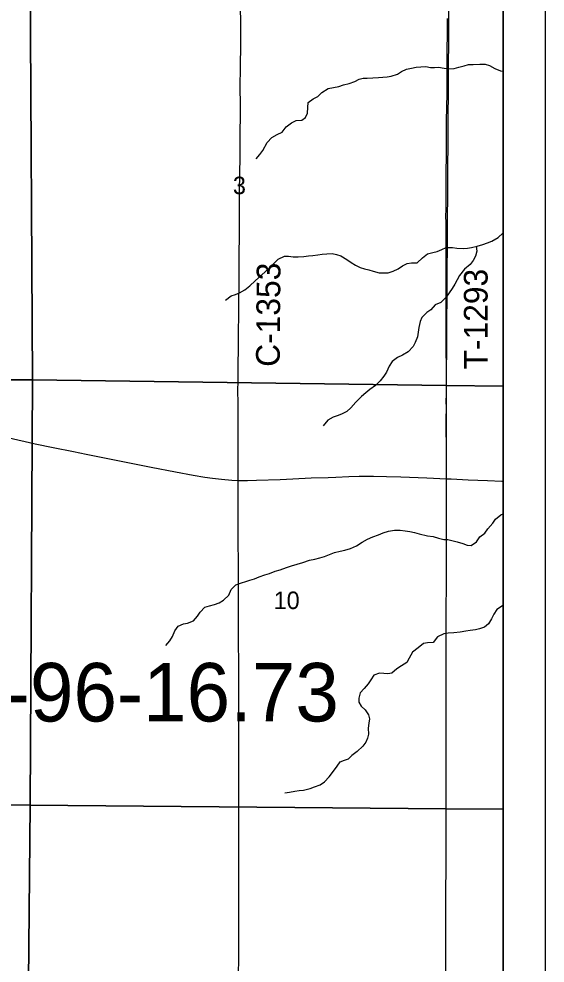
# Model space of a CAD drawing. Extents: x 0 to 70.2, y 0 to 31.4.
# Drawn here: x 7.741 to 9, y 15.952 to 18.211 of the extents above; entities that cross this region are included whole.
import ezdxf

# ---------------------------------------------------------------- set-up
doc = ezdxf.new("R2010")
doc.units = 0
for name, color, linetype in [('Default', 7, 'Continuous'), ('GM_X_County_Road', 7, 'Continuous'), ('GM_X_County_Road_Text', 7, 'Continuous'), ('GM_X_Minor_River', 7, 'Continuous'), ('GM_X_Section', 7, 'Continuous'), ('GM_X_Section_Text', 7, 'Continuous'), ('GM_X_State_Route', 7, 'Continuous'), ('GM_X_Township_Road', 7, 'Continuous'), ('GM_X_Township_Road_Text', 7, 'Continuous'), ('SH_Cut_Line', 7, 'Continuous'), ('SH_Data', 7, 'Continuous')]:
    doc.layers.add(name, color=color, linetype=linetype)

msp = doc.modelspace()

# ---------------------------------------------------------------- linework, layer by layer
at = {"layer": 'GM_X_County_Road'}
msp.add_lwpolyline([(8.2656, 17.1069), (8.2656, 17.113), (8.2658, 17.1534), (8.2658, 17.1814), (8.2656, 17.2311), (8.2655, 17.2621), (8.2655, 17.2869), (8.2653, 17.327), (8.2655, 17.3393), (8.2655, 17.3521), (8.2659, 17.386), (8.266, 17.3953), (8.2662, 17.4108), (8.2666, 17.4388), (8.2667, 17.4668), (8.267, 17.4978), (8.2676, 17.5382), (8.2679, 17.5724), (8.2681, 17.5942), (8.2681, 17.6065), (8.268, 17.622), (8.2679, 17.6282), (8.2681, 17.6438), (8.2684, 17.6653), (8.2686, 17.6748), (8.2688, 17.683), (8.2688, 17.7544), (8.2692, 17.798), (8.2707, 17.8819), (8.2708, 17.9254), (8.271, 17.9937), (8.271, 18.0154), (8.2709, 18.0372), (8.2716, 18.1056), (8.2719, 18.1398), (8.2719, 18.174), (8.2714, 18.2672)], dxfattribs=at)
at = {"layer": 'GM_X_Minor_River'}
for points in [[(8.3092, 17.8761), (8.3179, 17.8867), (8.3248, 17.8962), (8.3354, 17.9152), (8.346, 17.9269), (8.3589, 17.9345), (8.371, 17.9402), (8.3802, 17.9531), (8.3931, 17.9622), (8.4048, 17.9679), (8.4177, 17.969), (8.4272, 17.9754), (8.4314, 17.9857), (8.4321, 17.999), (8.4329, 18.0107), (8.4454, 18.0198), (8.456, 18.0251), (8.4659, 18.0346), (8.4807, 18.0441), (8.4936, 18.0467), (8.5069, 18.0494), (8.5175, 18.0528), (8.5315, 18.0562), (8.5448, 18.0611), (8.555, 18.0664), (8.5645, 18.0695), (8.5744, 18.0695), (8.5877, 18.0698), (8.6013, 18.0706), (8.6116, 18.0713), (8.6218, 18.0725), (8.6317, 18.074), (8.6468, 18.0789), (8.6563, 18.085), (8.6681, 18.0903), (8.6802, 18.0929), (8.6916, 18.0952), (8.703, 18.0963), (8.7147, 18.0967), (8.7257, 18.0948), (8.7356, 18.0948), (8.7451, 18.0955), (8.7587, 18.0929), (8.7693, 18.0914), (8.7826, 18.0925), (8.794, 18.0955), (8.8065, 18.0989), (8.8171, 18.1019), (8.8281, 18.1016), (8.8437, 18.1023), (8.8566, 18.1023), (8.8668, 18.0996), (8.8801, 18.092), (8.893, 18.0867), (8.9, 18.0862)], [(8.2351, 17.5377), (8.2487, 17.5483), (8.259, 17.5513), (8.2688, 17.5555), (8.2817, 17.5631), (8.2935, 17.5722), (8.3068, 17.5847), (8.3307, 17.6059), (8.3409, 17.6154), (8.3504, 17.6253), (8.3614, 17.6363), (8.3762, 17.6431), (8.3864, 17.6431), (8.3974, 17.6419), (8.4096, 17.6419), (8.4229, 17.6427), (8.4342, 17.6438), (8.4441, 17.6453), (8.4562, 17.6468), (8.4668, 17.648), (8.4775, 17.6487), (8.4904, 17.6495), (8.5006, 17.6476), (8.5112, 17.6441), (8.5256, 17.6354), (8.5362, 17.6278), (8.5465, 17.6217), (8.5575, 17.6164), (8.5681, 17.6134), (8.578, 17.6107), (8.5889, 17.6073), (8.6034, 17.6035), (8.6136, 17.6031), (8.6246, 17.6038), (8.6367, 17.6076), (8.6485, 17.6133), (8.6591, 17.6201), (8.6701, 17.6258), (8.6807, 17.627), (8.6936, 17.6273), (8.7065, 17.6391), (8.7183, 17.6486), (8.7316, 17.652), (8.7414, 17.6542), (8.7528, 17.6592), (8.7634, 17.6641), (8.7786, 17.6641), (8.7888, 17.6626), (8.8036, 17.6614), (8.8146, 17.6622), (8.8241, 17.6644), (8.8374, 17.6675), (8.8514, 17.6713), (8.8624, 17.6754), (8.8727, 17.6792), (8.8878, 17.6879), (8.8988, 17.6982), (8.9, 17.6977)], [(8.8353, 17.667), (8.837, 17.6549), (8.8336, 17.6436), (8.8275, 17.6333), (8.8207, 17.6235), (8.8074, 17.6125), (8.7949, 17.5973), (8.7896, 17.5867), (8.7842, 17.5764), (8.7774, 17.5658), (8.7706, 17.5556), (8.7634, 17.5453), (8.7508, 17.5328), (8.7372, 17.5271), (8.7269, 17.515), (8.7167, 17.5089), (8.7049, 17.4968), (8.7011, 17.4869), (8.6981, 17.4729), (8.6966, 17.4615), (8.6947, 17.4501), (8.6894, 17.4369), (8.6844, 17.4274), (8.6723, 17.4141), (8.6586, 17.4061), (8.6465, 17.4012), (8.6343, 17.3914), (8.6271, 17.38), (8.6207, 17.3659), (8.6146, 17.3561), (8.6051, 17.3451), (8.5941, 17.3337), (8.5808, 17.3246), (8.5714, 17.3166), (8.5604, 17.3079), (8.5471, 17.2939), (8.5353, 17.2802), (8.5254, 17.2715), (8.5148, 17.2658), (8.5053, 17.2624), (8.4932, 17.2579), (8.4803, 17.2507), (8.4689, 17.2378)], [(8.0924, 16.7121), (8.1023, 16.7235), (8.1084, 16.7337), (8.1141, 16.747), (8.1224, 16.758), (8.1346, 16.7637), (8.1444, 16.7656), (8.1592, 16.7709), (8.1687, 16.7819), (8.1748, 16.7921), (8.1858, 16.8035), (8.1968, 16.8065), (8.2093, 16.8099), (8.2203, 16.8137), (8.2309, 16.8201), (8.2431, 16.8323), (8.2488, 16.8463), (8.2601, 16.8573), (8.2734, 16.8619), (8.2844, 16.8649), (8.2939, 16.8679), (8.3045, 16.8717), (8.3163, 16.8759), (8.3296, 16.8808), (8.3406, 16.8846), (8.3546, 16.8895), (8.3663, 16.8933), (8.3815, 16.8986), (8.3937, 16.9024), (8.4069, 16.9069), (8.4206, 16.9107), (8.4361, 16.916), (8.449, 16.9187), (8.4612, 16.9217), (8.4722, 16.9247), (8.4843, 16.93), (8.4965, 16.9346), (8.5101, 16.938), (8.5207, 16.9403), (8.5344, 16.9444), (8.5488, 16.9505), (8.5625, 16.9592), (8.5753, 16.966), (8.5875, 16.9721), (8.6011, 16.9766), (8.6129, 16.9812), (8.6254, 16.9853), (8.6398, 16.9876), (8.6531, 16.9876), (8.6649, 16.9865), (8.6762, 16.9846), (8.6872, 16.9823), (8.699, 16.9792), (8.7187, 16.9747), (8.732, 16.9728), (8.7453, 16.969), (8.7574, 16.9652), (8.7672, 16.9659), (8.7767, 16.9632), (8.7896, 16.9598), (8.8029, 16.9556), (8.8135, 16.9518), (8.8234, 16.9511), (8.8355, 16.9598), (8.8439, 16.9723), (8.856, 16.9807), (8.8632, 16.9909), (8.875, 17.0049), (8.881, 17.0144), (8.8943, 17.0243), (8.9, 17.0269)], [(8.9, 16.8072), (8.8984, 16.8072), (8.8847, 16.7981), (8.8775, 16.7867), (8.8718, 16.7757), (8.8646, 16.764), (8.8547, 16.756), (8.8434, 16.7515), (8.8331, 16.7496), (8.8206, 16.7477), (8.81, 16.7462), (8.7971, 16.7435), (8.7819, 16.742), (8.7679, 16.7413), (8.7577, 16.7398), (8.7425, 16.7326), (8.7319, 16.7193), (8.7186, 16.7182), (8.7087, 16.7167), (8.6962, 16.706), (8.6829, 16.6958), (8.6746, 16.6818), (8.6689, 16.6711), (8.6567, 16.6632), (8.645, 16.6564), (8.6332, 16.6461), (8.6237, 16.6438), (8.6139, 16.6446), (8.6036, 16.6458), (8.5904, 16.6408), (8.5835, 16.6298), (8.5771, 16.62), (8.5672, 16.6094), (8.5577, 16.5984), (8.5543, 16.5862), (8.5547, 16.5767), (8.56, 16.5665), (8.5695, 16.5577), (8.5778, 16.5464), (8.5801, 16.5369), (8.5785, 16.5259), (8.5766, 16.5141), (8.5778, 16.5001), (8.5755, 16.4906), (8.5709, 16.4807), (8.5637, 16.4709), (8.5501, 16.4587), (8.5379, 16.4492)], [(8.3771, 16.3597), (8.3884, 16.3615), (8.4013, 16.3637), (8.4118, 16.3651), (8.422, 16.3661), (8.4379, 16.3702), (8.4484, 16.3735), (8.4619, 16.3788), (8.472, 16.3855), (8.4838, 16.3975), (8.4941, 16.411), (8.5026, 16.4234), (8.5099, 16.4334), (8.52, 16.4378), (8.5298, 16.4411), (8.5379, 16.4492)]]:
    msp.add_lwpolyline(points, dxfattribs=at)
at = {"layer": 'GM_X_Section'}
for points in [[(7.7683, 18.3114), (7.7735, 17.3473), (6.7779, 17.3473), (6.7772, 18.3092)], [(8.7699, 18.3113), (8.763, 17.3339), (7.7735, 17.3473), (7.7683, 18.3114)], [(6.7779, 17.3473), (7.7735, 17.3473), (7.7683, 16.3298), (6.7778, 16.3386)], [(7.7735, 17.3473), (8.763, 17.3339), (8.7624, 16.321), (7.7683, 16.3298)], [(6.7778, 16.3386), (7.7683, 16.3298), (7.7584, 15.3168), (6.7706, 15.321)], [(7.7683, 16.3298), (8.7624, 16.321), (8.7601, 15.3035), (7.7584, 15.3168)]]:
    msp.add_lwpolyline(points, close=True, dxfattribs=at)
at = {"layer": 'GM_X_Section_Text'}
msp.add_lwpolyline([(8.9, 14.1), (8.9, 18.3173)], dxfattribs=at)
at = {"layer": 'GM_X_State_Route'}
for points in [[(8.9, 17.3322), (8.9, 18.3109), (8.7726, 18.3113), (8.7699, 18.3113), (8.763, 17.3339)], [(8.9, 16.3205), (8.9, 17.3322), (8.763, 17.3339), (8.7624, 16.321)], [(8.9, 15.3035), (8.9, 16.3205), (8.7624, 16.321), (8.7601, 15.3035)]]:
    msp.add_lwpolyline(points, close=True, dxfattribs=at)
msp.add_lwpolyline([(7.7107, 17.2107), (7.756, 17.2), (7.7803, 17.1947), (7.8229, 17.1859), (7.8717, 17.1762), (7.9021, 17.1699), (7.9418, 17.162), (8.0576, 17.1389), (8.1156, 17.1276), (8.1583, 17.1194), (8.1859, 17.1146), (8.2044, 17.112), (8.226, 17.1096), (8.2509, 17.1076), (8.2656, 17.1069), (8.2695, 17.1067), (8.2882, 17.1066), (8.31, 17.1071), (8.3659, 17.1094), (8.3969, 17.1108), (8.4404, 17.1127), (8.4808, 17.114), (8.4994, 17.1149), (8.5304, 17.1163), (8.5553, 17.1168), (8.5894, 17.1168), (8.6205, 17.1163), (8.6547, 17.1156), (8.7167, 17.1133), (8.7644, 17.1109), (8.7756, 17.1104), (8.816, 17.1084), (8.8625, 17.1064), (8.8967, 17.1049), (8.9, 17.1047)], dxfattribs=at)
at = {"layer": 'GM_X_Township_Road'}
for points in [[(8.2656, 17.1069), (8.2656, 17.113), (8.2658, 17.1534), (8.2658, 17.1814), (8.2656, 17.2311), (8.2655, 17.2621), (8.2655, 17.2869), (8.2653, 17.327), (8.2655, 17.3393), (8.2655, 17.3521), (8.2659, 17.386), (8.266, 17.3953), (8.2662, 17.4108), (8.2666, 17.4388), (8.2667, 17.4668), (8.267, 17.4978), (8.2676, 17.5382), (8.2679, 17.5724), (8.2681, 17.5942), (8.2681, 17.6065), (8.268, 17.622), (8.2679, 17.6282), (8.2681, 17.6438), (8.2684, 17.6653), (8.2686, 17.6748), (8.2688, 17.683), (8.2688, 17.7544), (8.2692, 17.798), (8.2707, 17.8819), (8.2708, 17.9254), (8.271, 17.9937), (8.271, 18.0154), (8.2709, 18.0372), (8.2716, 18.1056), (8.2719, 18.1398), (8.2719, 18.174), (8.2714, 18.2672)], [(8.7644, 17.1109), (8.7645, 17.1164), (8.7644, 17.1475), (8.7643, 17.1692), (8.764, 17.1847), (8.7639, 17.194), (8.7637, 17.2251), (8.7637, 17.2561), (8.7638, 17.2779), (8.7634, 17.2996), (8.7638, 17.3089), (8.7638, 17.368), (8.7639, 17.3835), (8.7637, 17.4146), (8.7637, 17.4643), (8.7632, 17.5845), (8.7636, 17.6465), (8.7637, 17.6652), (8.7637, 17.6841), (8.7633, 17.7024), (8.763, 17.7239), (8.7629, 17.7393), (8.7632, 17.7553), (8.7633, 17.7769), (8.7635, 17.7984), (8.7635, 17.8143), (8.7637, 17.8301), (8.7637, 17.8419), (8.7641, 17.8854), (8.7642, 17.9196), (8.7643, 17.9445), (8.7645, 17.9693), (8.7649, 17.9973), (8.7655, 18.0346), (8.7656, 18.0471), (8.7658, 18.0596), (8.7656, 18.078), (8.7656, 18.0936), (8.7657, 18.1153), (8.7659, 18.1308), (8.766, 18.1462), (8.7664, 18.1651), (8.7668, 18.2116)], [(8.2669, 15.9149), (8.2672, 15.9739), (8.2671, 16.0174), (8.2673, 16.0857), (8.2675, 16.1137), (8.2676, 16.1479), (8.2673, 16.1851), (8.2677, 16.2224), (8.2676, 16.2877), (8.2673, 16.3622), (8.2673, 16.4399), (8.2672, 16.5455), (8.2674, 16.5921), (8.2671, 16.6076), (8.2673, 16.6416), (8.2673, 16.6633), (8.2665, 16.7256), (8.2664, 16.7847), (8.2665, 16.8344), (8.2663, 16.9058), (8.2661, 16.9648), (8.266, 17.027), (8.2658, 17.0979), (8.2656, 17.1069)]]:
    msp.add_lwpolyline(points, dxfattribs=at)
at = {"layer": 'SH_Cut_Line'}
msp.add_lwpolyline([(8.9, 14.1), (8.9, 20.9)], dxfattribs=at)
at = {"layer": 'SH_Data'}
for p, q in [((9, 21), (9, 14)), ((8.9, 20.9), (8.9, 14.1))]:
    msp.add_line(p, q, dxfattribs=at)

# ---------------------------------------------------------------- texts
at = {"layer": 'Default'}
msp.add_text('RIC-96-16.73', height=0.14, dxfattribs=at).set_placement((7.3829, 16.5302))
at = {"layer": 'GM_X_County_Road_Text'}
msp.add_text('C-1353', height=0.05682, rotation=89.5457, dxfattribs=at).set_placement((8.3651, 17.3784))
at = {"layer": 'GM_X_Section_Text'}
for s, height, p in [('3', 0.0419, (8.2531, 17.7916)), ('10', 0.04186, (8.3506, 16.7991))]:
    msp.add_text(s, height=height, rotation=0, dxfattribs=at).set_placement(p)
at = {"layer": 'GM_X_Township_Road_Text'}
msp.add_text('T-1293', height=0.05682, rotation=90, dxfattribs=at).set_placement((8.8625, 17.3723))

doc.saveas('drawing.dxf')
